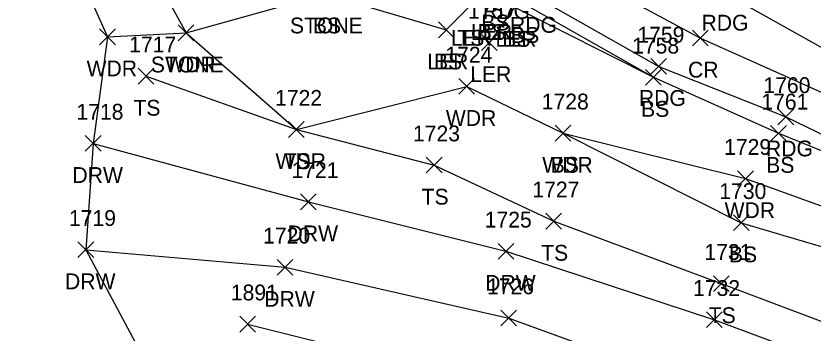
# Model space of a CAD drawing. Extents: x 1512665 to 1513714, y 110636 to 112816.
# Drawn here: x 1512668.9 to 1512769.8, y 110869.1 to 110909.2 of the extents above; entities that cross this region are included whole.
import ezdxf

# ---------------------------------------------------------------- set-up
doc = ezdxf.new("R2010")
doc.units = 0
for name, color, linetype in [('L_A', 7, 'Continuous'), ('L_I', 7, 'Continuous'), ('L_TIC', 7, 'Continuous'), ('LARO', 7, 'Continuous'), ('LASF', 7, 'Continuous'), ('LAWA', 7, 'Continuous'), ('LELB', 7, 'Continuous'), ('LSOGP', 7, 'Continuous'), ('P_A', 7, 'Continuous'), ('P_I', 7, 'Continuous'), ('P_TIC', 7, 'Continuous'), ('PEU', 7, 'Continuous'), ('PRC', 7, 'Continuous'), ('R_A', 7, 'Continuous'), ('R_I', 7, 'Continuous'), ('R_TIC', 7, 'Continuous'), ('RDW', 7, 'Continuous')]:
    doc.layers.add(name, color=color, linetype=linetype)

msp = doc.modelspace()

# ---------------------------------------------------------------- linework, layer by layer
at = {"layer": 'L_TIC'}
for points in [[(1512722.36, 110906.48), (1512724.36, 110908.48)], [(1512724.36, 110906.48), (1512722.36, 110908.48)], [(1512722.36, 110906.48), (1512724.36, 110908.48)], [(1512724.36, 110906.48), (1512722.36, 110908.48)], [(1512679.49, 110905.6), (1512681.49, 110907.6)], [(1512681.49, 110905.6), (1512679.49, 110907.6)], [(1512689.44, 110906.09), (1512691.44, 110908.09)], [(1512691.44, 110906.09), (1512689.44, 110908.09)], [(1512689.44, 110906.09), (1512691.44, 110908.09)], [(1512691.44, 110906.09), (1512689.44, 110908.09)], [(1512727.81, 110904.87), (1512729.81, 110906.87)], [(1512729.81, 110904.87), (1512727.81, 110906.87)], [(1512684.37, 110900.62), (1512686.37, 110902.62)], [(1512686.37, 110900.62), (1512684.37, 110902.62)], [(1512748.56, 110900.48), (1512750.56, 110902.48)], [(1512750.56, 110900.48), (1512748.56, 110902.48)], [(1512748.56, 110900.48), (1512750.56, 110902.48)], [(1512750.56, 110900.48), (1512748.56, 110902.48)], [(1512724.94, 110899.33), (1512726.94, 110901.33)], [(1512726.94, 110899.33), (1512724.94, 110901.33)], [(1512703.39, 110893.87), (1512705.39, 110895.87)], [(1512705.39, 110893.87), (1512703.39, 110895.87)], [(1512703.39, 110893.87), (1512705.39, 110895.87)], [(1512705.39, 110893.87), (1512703.39, 110895.87)], [(1512737.13, 110893.41), (1512739.13, 110895.41)], [(1512739.13, 110893.41), (1512737.13, 110895.41)], [(1512737.13, 110893.41), (1512739.13, 110895.41)], [(1512739.13, 110893.41), (1512737.13, 110895.41)], [(1512764.39, 110893.4), (1512766.39, 110895.4)], [(1512766.39, 110893.4), (1512764.39, 110895.4)], [(1512720.83, 110889.38), (1512722.83, 110891.38)], [(1512722.83, 110889.38), (1512720.83, 110891.38)], [(1512760.21, 110887.67), (1512762.21, 110889.67)], [(1512762.21, 110887.67), (1512760.21, 110889.67)], [(1512735.95, 110882.29), (1512737.95, 110884.29)], [(1512737.95, 110882.29), (1512735.95, 110884.29)], [(1512759.68, 110882.09), (1512761.68, 110884.09)], [(1512761.68, 110882.09), (1512759.68, 110884.09)], [(1512757.15, 110874.39), (1512759.15, 110876.39)], [(1512759.15, 110874.39), (1512757.15, 110876.39)], [(1512697.23, 110869.27), (1512699.23, 110871.27)], [(1512699.23, 110869.27), (1512697.23, 110871.27)]]:
    msp.add_lwpolyline(points, dxfattribs=at)
at = {"layer": 'LARO'}
msp.add_lwpolyline([(1512723.36, 110907.48), (1512726.35, 110910.47), (1512728.9, 110911.2), (1512732, 110910.33), (1512728.81, 110905.87)], dxfattribs=at)
at = {"layer": 'LASF'}
msp.add_lwpolyline([(1512685.13, 110931.6), (1512684.85, 110917.24), (1512690.44, 110907.09), (1512708.03, 110912.03)], dxfattribs=at)
at = {"layer": 'LAWA'}
msp.add_lwpolyline([(1512680.49, 110906.6), (1512690.44, 110907.09), (1512704.39, 110894.87), (1512725.94, 110900.33), (1512738.13, 110894.41), (1512761.21, 110888.67), (1512781.15, 110881.47), (1512810.21, 110864.84), (1512817.69, 110861.88), (1512832.48, 110853.08), (1512847.52, 110845.49), (1512864.92, 110836.03), (1512870.72, 110832.57), (1512881.89, 110825.79), (1512904.86, 110814.16), (1512921.13, 110807.47)], dxfattribs=at)
at = {"layer": 'LELB'}
for points in [[(1512700.68, 110948.39), (1512702.88, 110937.76), (1512707.7, 110928.25), (1512715.73, 110919.82), (1512729.36, 110912.4), (1512733.11, 110910.82), (1512749.56, 110901.48), (1512765.39, 110894.4), (1512774.13, 110890.87), (1512779.73, 110888.58), (1512784.33, 110885.95), (1512807.05, 110874.73), (1512832.03, 110862.15), (1512849.87, 110852.9), (1512877.54, 110837.79), (1512892.07, 110830.38), (1512907.92, 110822.22), (1512921.56, 110815.36), (1512936.61, 110807.63), (1512945.8, 110795.18), (1512949.9, 110789.74), (1512950.99, 110781.57)], [(1512708.03, 110912.03), (1512723.36, 110907.48)], [(1512732, 110910.33), (1512749.56, 110901.48)], [(1512685.37, 110901.62), (1512704.39, 110894.87), (1512721.83, 110890.38), (1512736.95, 110883.29), (1512758.15, 110875.39), (1512778.26, 110867.83), (1512805.48, 110853.5), (1512829.24, 110847.86), (1512845.12, 110839.12), (1512864.92, 110836.03)], [(1512738.13, 110894.41), (1512760.68, 110883.09), (1512779.76, 110877.43), (1512809.28, 110861.94), (1512816.23, 110858.7), (1512830.12, 110852.43), (1512847.52, 110845.49)], [(1512698.23, 110870.27), (1512729.45, 110862.45), (1512749.63, 110850.69), (1512777.7, 110834.64), (1512793.92, 110831.75), (1512815.55, 110826.53), (1512828.48, 110824.79), (1512839.13, 110821.43), (1512854.65, 110808.75), (1512864.61, 110809.77)]]:
    msp.add_lwpolyline(points, dxfattribs=at)
at = {"layer": 'LSOGP'}
msp.add_lwpolyline([(1512785.1, 111051.82), (1512750.15, 111051.93), (1512743.48, 111053.43), (1512731.78, 111051.67), (1512710.4, 111049.29), (1512701.92, 111049.68), (1512693.67, 111049.35), (1512687.76, 111048.12), (1512685.96, 111048.51), (1512683.49, 111048.69), (1512677.5, 111048.51), (1512677.69, 111023.86), (1512677.11, 110992.56), (1512680.98, 110966.17), (1512682.8, 110958.12), (1512681.34, 110951.55), (1512668.91, 110930.04), (1512674.4, 110920.19), (1512680.5, 110906.6), (1512678.7, 110893.12), (1512677.75, 110879.68), (1512694.93, 110847.53)], dxfattribs=at)
at = {"layer": 'P_TIC'}
for points in [[(1512754.51, 110905.44), (1512756.51, 110907.44)], [(1512756.51, 110905.44), (1512754.51, 110907.44)], [(1512749.23, 110901.86), (1512751.23, 110903.86)], [(1512751.23, 110901.86), (1512749.23, 110903.86)], [(1512765.31, 110895.48), (1512767.31, 110897.48)], [(1512767.31, 110895.48), (1512765.31, 110897.48)]]:
    msp.add_lwpolyline(points, dxfattribs=at)
at = {"layer": 'PEU'}
for points in [[(1512701.92, 111049.69), (1512700.27, 111027.69), (1512701.57, 110993.78), (1512707.63, 110973.74), (1512708.97, 110956.47), (1512713.57, 110946.9), (1512719.22, 110936.54), (1512726.89, 110929.38), (1512741.61, 110919.6), (1512758.16, 110912.38), (1512787.35, 110896), (1512813.05, 110887.98), (1512838.37, 110874.78), (1512855.92, 110864.84), (1512882.82, 110848.35), (1512898.24, 110841.37), (1512913.49, 110833.4), (1512927.92, 110827.38), (1512944.46, 110817.21), (1512962.88, 110803.83), (1512982.13, 110789.05), (1512997.25, 110777.45), (1513011.32, 110770.56), (1513024, 110765.99)], [(1512687.75, 111048.12), (1512689.18, 111024.57), (1512692.04, 110992.51), (1512695.11, 110971.67), (1512700.68, 110948.39), (1512706.36, 110937.56), (1512711.03, 110929.61), (1512717.58, 110922.71), (1512730.52, 110913.86), (1512733.94, 110912.11), (1512750.23, 110902.86), (1512766.31, 110896.48), (1512784.35, 110887.76), (1512808.18, 110876.47), (1512833.24, 110864.02), (1512850.68, 110854.9), (1512878.02, 110839.24), (1512892.94, 110831.72), (1512908.54, 110823.76), (1512922.46, 110816.85)]]:
    msp.add_lwpolyline(points, dxfattribs=at)
at = {"layer": 'PRC'}
msp.add_lwpolyline([(1512693.67, 111049.35), (1512695.61, 111024.36), (1512696.79, 110993.28), (1512701.08, 110972.95), (1512704.1, 110953.94), (1512709.81, 110942.45), (1512716.01, 110931.96), (1512724.47, 110925.17), (1512739.89, 110914.85), (1512755.51, 110906.44), (1512786.55, 110892.54), (1512810.31, 110881.66), (1512835.15, 110868.41), (1512852.56, 110858.81), (1512880.61, 110843.33), (1512895.52, 110835.81), (1512910.92, 110828.7), (1512924.7, 110822.05)], dxfattribs=at)
at = {"layer": 'R_TIC'}
for points in [[(1512677.69, 110892.12), (1512679.69, 110894.12)], [(1512679.69, 110892.12), (1512677.69, 110894.12)], [(1512704.91, 110884.74), (1512706.91, 110886.74)], [(1512706.91, 110884.74), (1512704.91, 110886.74)], [(1512676.75, 110878.68), (1512678.75, 110880.68)], [(1512678.75, 110878.68), (1512676.75, 110880.68)], [(1512729.91, 110878.48), (1512731.91, 110880.48)], [(1512731.91, 110878.48), (1512729.91, 110880.48)], [(1512701.96, 110876.46), (1512703.96, 110878.46)], [(1512703.96, 110876.46), (1512701.96, 110878.46)], [(1512730.26, 110870.04), (1512732.26, 110872.04)], [(1512732.26, 110870.04), (1512730.26, 110872.04)], [(1512756.28, 110869.83), (1512758.28, 110871.83)], [(1512758.28, 110869.83), (1512756.28, 110871.83)]]:
    msp.add_lwpolyline(points, dxfattribs=at)
at = {"layer": 'RDW'}
for points in [[(1512678.69, 110893.12), (1512705.91, 110885.74), (1512730.91, 110879.48), (1512757.28, 110870.83), (1512775.98, 110863.85), (1512803.62, 110850.37), (1512827.04, 110842.82), (1512843.68, 110837.08), (1512859.31, 110829.49), (1512882.79, 110804.51), (1512900.46, 110800.08), (1512923.2, 110794.9)], [(1512677.75, 110879.68), (1512702.96, 110877.46), (1512731.26, 110871.04), (1512755.65, 110862.16), (1512771.64, 110855.39), (1512800.14, 110841.72), (1512826.02, 110832.15), (1512842.36, 110825.52), (1512852.9, 110823.11), (1512864.61, 110809.77), (1512882.31, 110793.7), (1512890.53, 110788.25), (1512897.02, 110786.49), (1512918.65, 110784.55)]]:
    msp.add_lwpolyline(points, dxfattribs=at)

# ---------------------------------------------------------------- texts
at = {"layer": 'L_A'}
for s, p in [('STONE', (1512703.58, 110907.03)), ('STONE', (1512703.58, 110907.03)), ('BS', (1512706.48, 110907.03)), ('BS', (1512727.8, 110907.4)), ('LER', (1512723.93, 110905.47)), ('TS', (1512724.76, 110905.47)), ('LER', (1512726.48, 110906.2)), ('BS', (1512727.34, 110906.2)), ('BS', (1512731.55, 110905.82)), ('LER', (1512729.58, 110905.33)), ('BS', (1512730.44, 110905.33)), ('LER', (1512720.95, 110902.48)), ('BS', (1512721.8, 110902.48)), ('WDR', (1512677.85, 110901.6)), ('STONE', (1512685.98, 110902.09)), ('WDR', (1512687.8, 110902.09)), ('LER', (1512726.39, 110900.87)), ('TS', (1512683.78, 110896.62)), ('BS', (1512748, 110896.48)), ('BS', (1512748, 110896.48)), ('WDR', (1512723.3, 110895.33)), ('WDR', (1512701.75, 110889.87)), ('TS', (1512702.8, 110889.87)), ('WDR', (1512735.5, 110889.41)), ('BS', (1512736.57, 110889.41)), ('BS', (1512763.83, 110889.4)), ('TS', (1512720.24, 110885.38)), ('WDR', (1512758.57, 110883.67)), ('TS', (1512735.36, 110878.29)), ('BS', (1512759.12, 110878.09)), ('TS', (1512756.56, 110870.39))]:
    msp.add_text(s, height=2, dxfattribs=at).set_placement(p)
at = {"layer": 'L_I'}
for s, p in [('1757', (1512726.12, 110908.87)), ('1717', (1512683.24, 110904.62)), ('1758', (1512746.87, 110904.48)), ('1758', (1512746.87, 110904.48)), ('1724', (1512723.24, 110903.33)), ('1722', (1512701.7, 110897.87)), ('1722', (1512701.7, 110897.87)), ('1728', (1512735.44, 110897.41)), ('1728', (1512735.44, 110897.41)), ('1761', (1512763.22, 110897.4)), ('1723', (1512719.14, 110893.38)), ('1729', (1512758.51, 110891.67)), ('1727', (1512734.25, 110886.29)), ('1730', (1512757.9, 110886.09)), ('1731', (1512756.02, 110878.39)), ('1891', (1512696.1, 110873.27))]:
    msp.add_text(s, height=2, dxfattribs=at).set_placement(p)
at = {"layer": 'P_A'}
for s, p in [('RDG', (1512728.01, 110908.86)), ('RDG', (1512731.42, 110907.11)), ('RDG', (1512755.65, 110907.38)), ('CR', (1512753.94, 110901.44)), ('RDG', (1512747.72, 110897.86)), ('RDG', (1512763.8, 110891.48))]:
    msp.add_text(s, height=2, dxfattribs=at).set_placement(p)
at = {"layer": 'P_I'}
for s, p in [('1759', (1512747.53, 110905.86)), ('1760', (1512763.48, 110899.48))]:
    msp.add_text(s, height=2, dxfattribs=at).set_placement(p)
at = {"layer": 'R_A'}
for p in [(1512676.06, 110888.12), (1512703.28, 110880.74), (1512675.12, 110874.68), (1512728.28, 110874.48), (1512700.33, 110872.46)]:
    msp.add_text('DRW', height=2, dxfattribs=at).set_placement(p)
at = {"layer": 'R_I'}
for s, p in [('1718', (1512676.57, 110896.12)), ('1721', (1512703.78, 110888.74)), ('1719', (1512675.62, 110882.68)), ('1725', (1512728.22, 110882.48)), ('1720', (1512700.18, 110880.46)), ('1726', (1512728.51, 110874.04)), ('1732', (1512754.58, 110873.83))]:
    msp.add_text(s, height=2, dxfattribs=at).set_placement(p)

doc.saveas('drawing.dxf')
